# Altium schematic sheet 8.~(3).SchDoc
size 599 x 434 mm
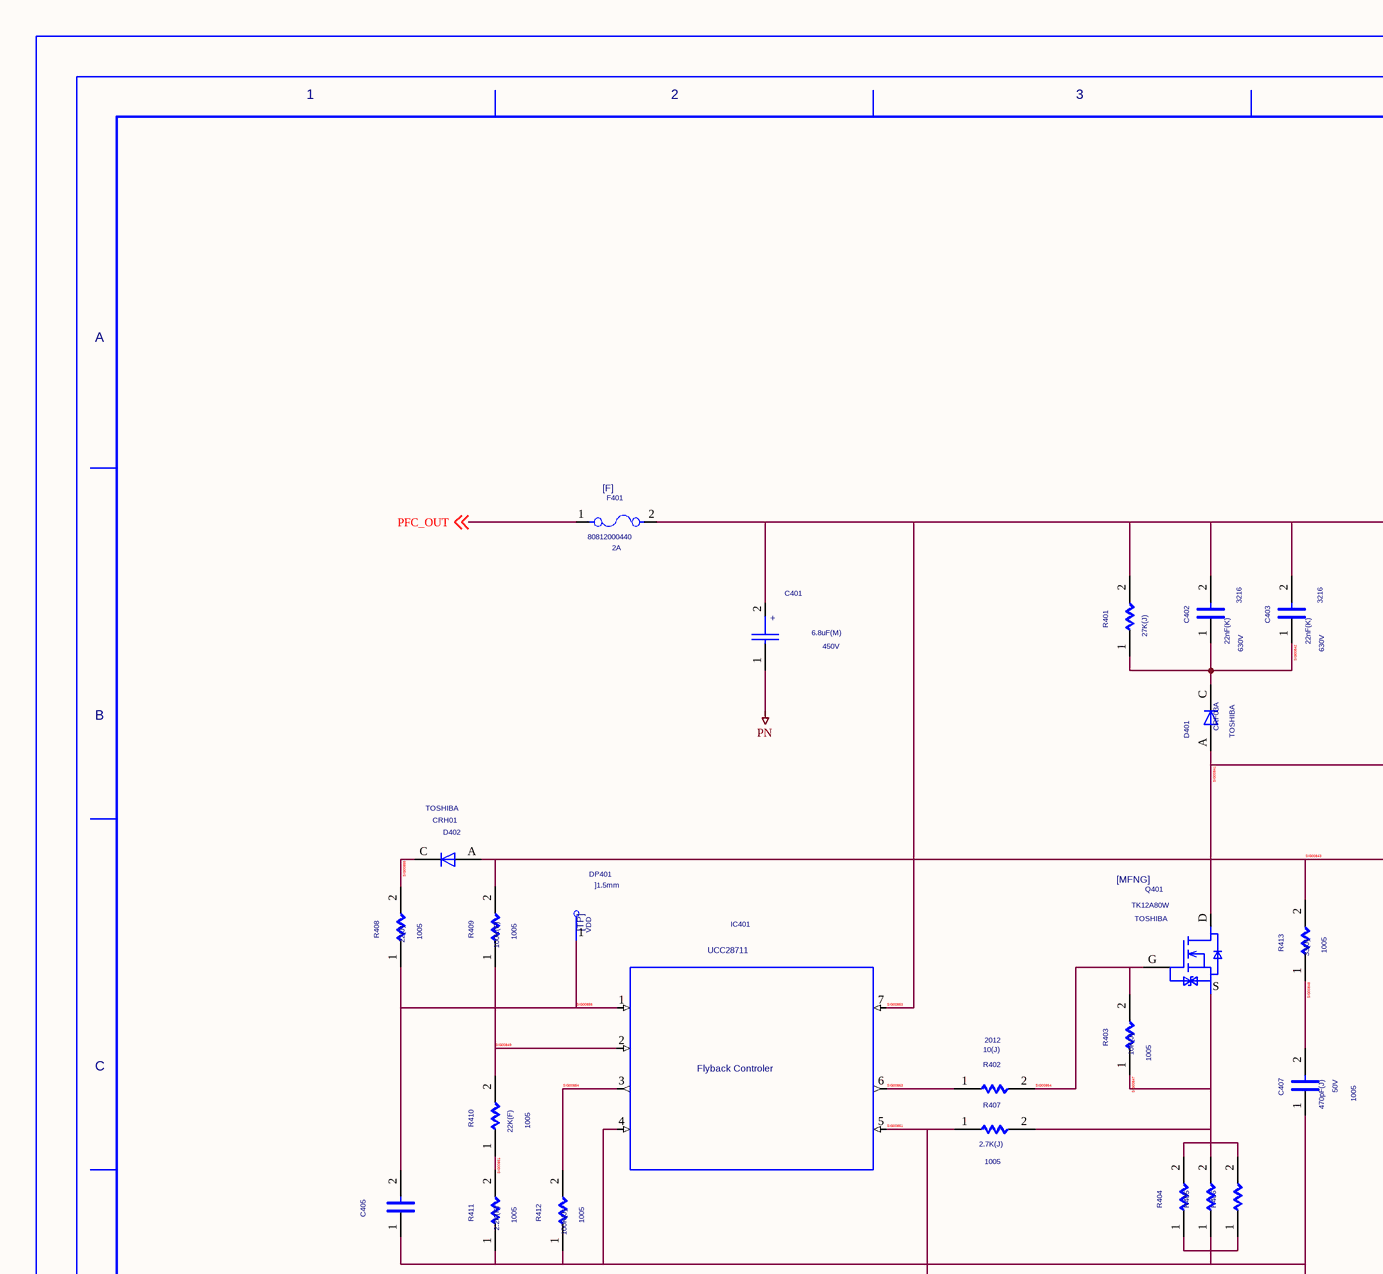
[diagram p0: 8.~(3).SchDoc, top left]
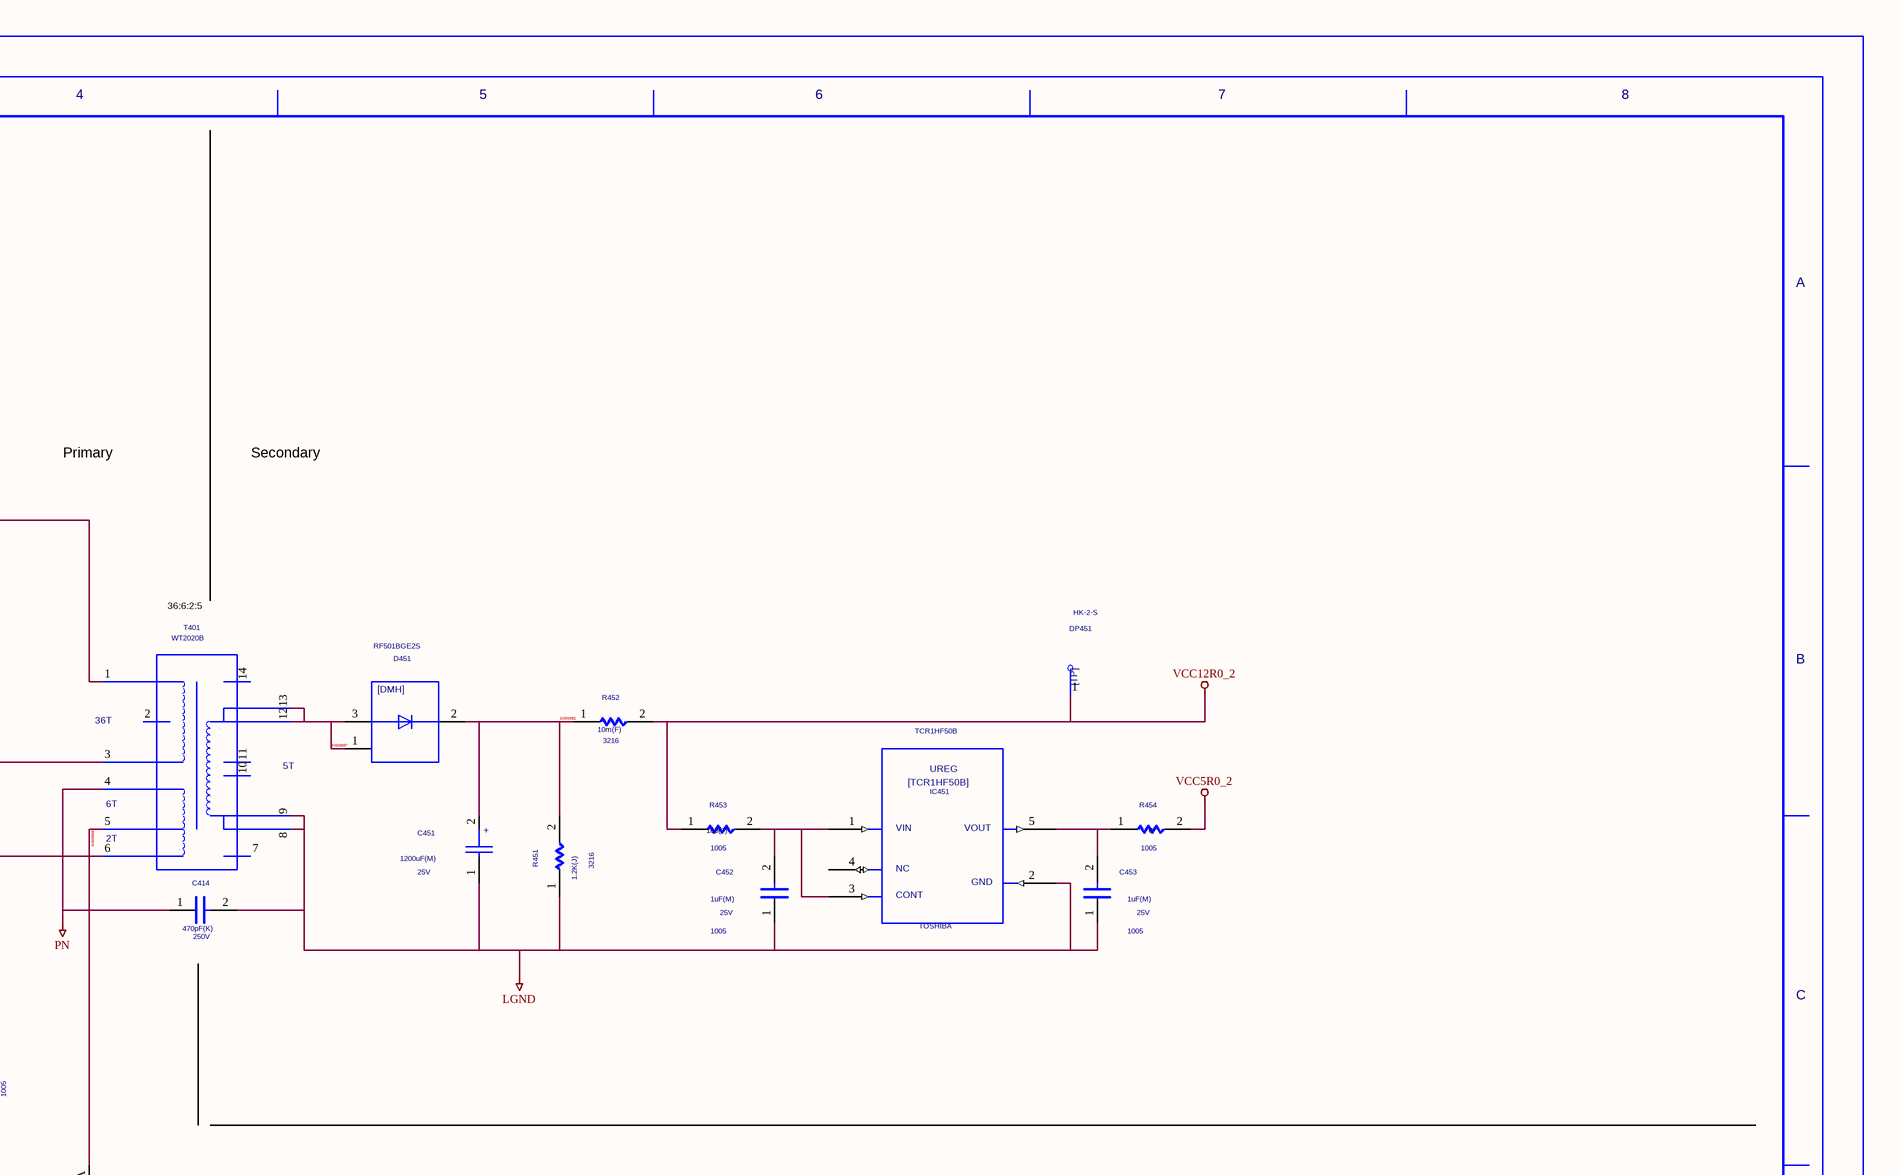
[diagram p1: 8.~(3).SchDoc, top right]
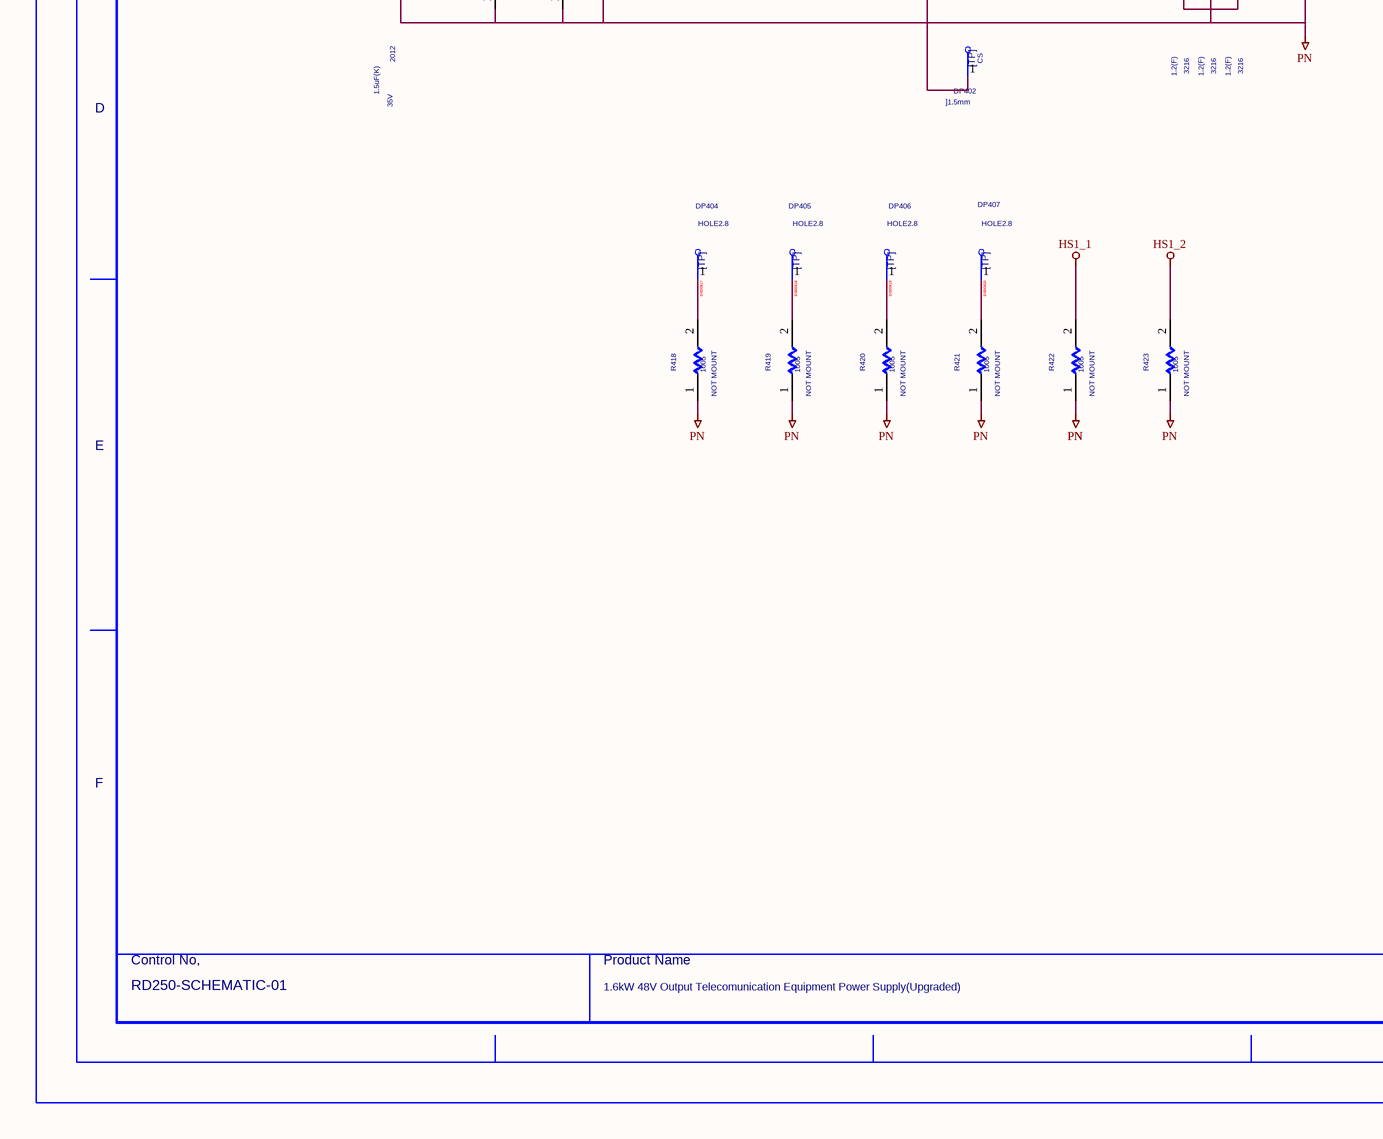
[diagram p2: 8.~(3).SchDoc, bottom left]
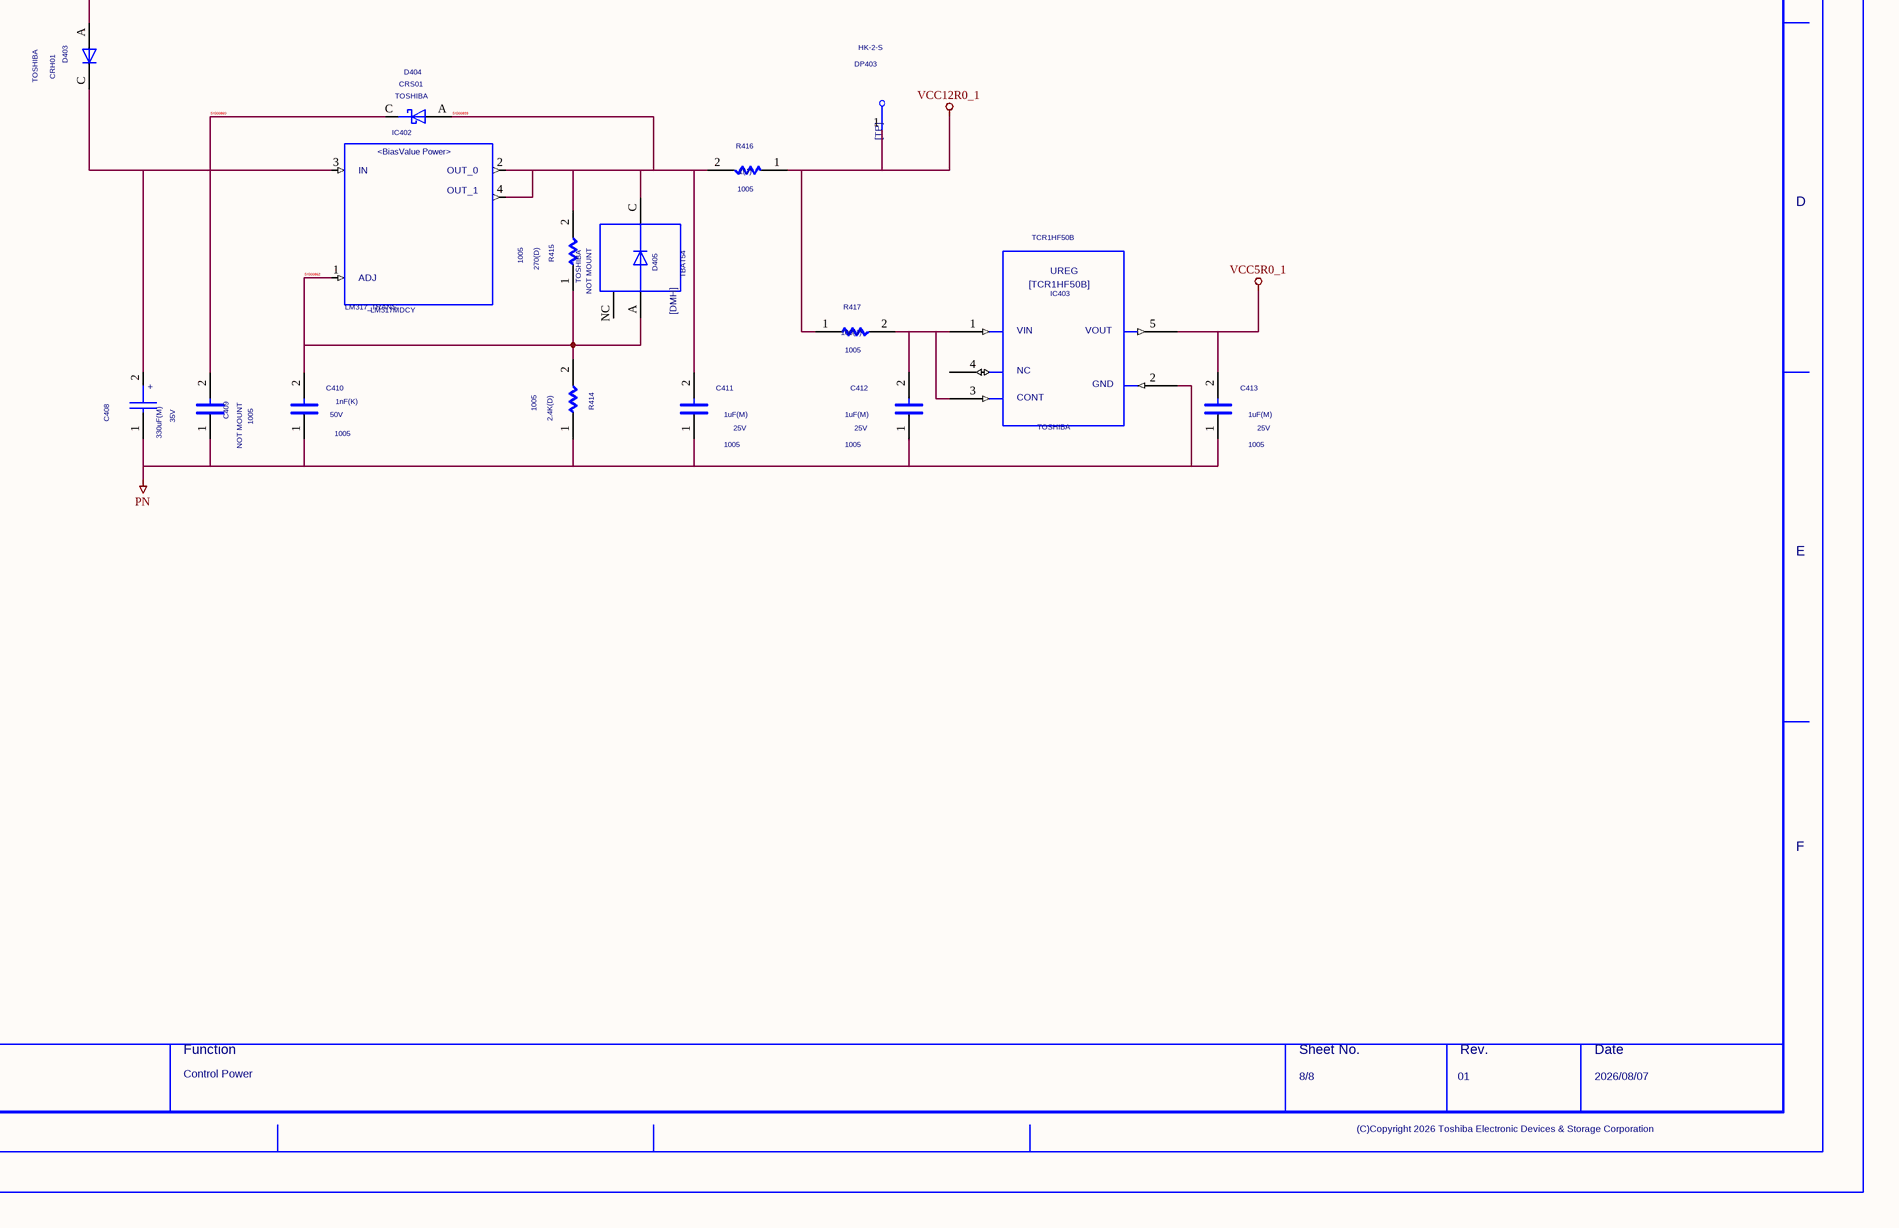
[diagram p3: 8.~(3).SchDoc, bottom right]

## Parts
C401  VAL1: 6.8uF(M)  VAL2: 450V  (hidden comment: CP)
C402  VAL1: 22nF(K)  VAL2: 630V  SIZECODESMD: 3216  (hidden comment: C)
C403  VAL1: 22nF(K)  VAL2: 630V  SIZECODESMD: 3216  (hidden comment: C)
C405  VAL1: 1.5uF(K)  VAL2: 35V  SIZECODESMD: 2012  (hidden comment: GRM21BC71E106KE01)
C407  VAL1: 470pF(J)  VAL2: 50V  SIZECODESMD: 1005  (hidden comment: C)
C408  VAL1: 330uF(M)  VAL2: 35V  (hidden comment: CP)
C409  NOTMOUNT: NOT MOUNT  SIZECODESMD: 1005  (hidden comment: C)
C410  VAL1: 1nF(K)  VAL2: 50V  SIZECODESMD: 1005  (hidden comment: C)
C411  VAL1: 1uF(M)  VAL2: 25V  SIZECODESMD: 1005  (hidden comment: C)
C412  VAL1: 1uF(M)  VAL2: 25V  SIZECODESMD: 1005  (hidden comment: C)
C413  VAL1: 1uF(M)  VAL2: 25V  SIZECODESMD: 1005  (hidden comment: C)
C414  VAL1: 470pF(K)  VAL2: 250V  (hidden comment: C)
C451  VAL1: 1200uF(M)  VAL2: 25V  (hidden comment: CP)
C452  VAL1: 1uF(M)  VAL2: 25V  SIZECODESMD: 1005  (hidden comment: C)
C453  VAL1: 1uF(M)  VAL2: 25V  SIZECODESMD: 1005  (hidden comment: C)
D401  USERCOMPTEXT3: TOSHIBA  VAL3: CRF03A  (hidden comment: D)
D402  USERCOMPTEXT3: TOSHIBA  VAL3: CRH01  (hidden comment: D)
D403  USERCOMPTEXT3: TOSHIBA  VAL3: CRH01  (hidden comment: D)
D404  USERCOMPTEXT3: TOSHIBA  VAL3: CRS01  (hidden comment: SBD)
D405  NOTMOUNT: NOT MOUNT  USERCOMPTEXT3: TOSHIBA  VAL3: TBAT54  (hidden comment: DMH)
D451  RF501BGE2S
DP401  COMPCOMMENT: VDD  USERCOMPTEXT1: ]1.5mm  (hidden comment: TP)
DP402  COMPCOMMENT: CS  USERCOMPTEXT1: ]1.5mm  (hidden comment: TP)
DP403  VAL3: HK-2-S  (hidden comment: TP)
DP404  VAL3: HOLE2.8  (hidden comment: TP)
DP405  VAL3: HOLE2.8  (hidden comment: TP)
DP406  VAL3: HOLE2.8  (hidden comment: TP)
DP407  VAL3: HOLE2.8  (hidden comment: TP)
DP451  VAL3: HK-2-S  (hidden comment: TP)
F401  VAL1: 2A  VAL3: 80812000440  (hidden comment: F)
IC401  UCC28711
IC402  LM317_TRANS  [DCY0004A_N]
IC403  USERCOMPTEXT3: TOSHIBA  (hidden comment: TCR1HF50B)
IC451  USERCOMPTEXT3: TOSHIBA  (hidden comment: TCR1HF50B)
Q401  USERCOMPTEXT3: TOSHIBA  VAL3: TK12A80W  (hidden comment: MFNF)
R401  VAL1: 27K(J)  (hidden comment: R)
R402  VAL1: 10(J)  SIZECODESMD: 2012  (hidden comment: R)
R403  VAL1: 10K(J)  SIZECODESMD: 1005  (hidden comment: R)
R404  VAL1: 1.2(F)  SIZECODESMD: 3216  (hidden comment: R)
R405  VAL1: 1.2(F)  SIZECODESMD: 3216  (hidden comment: R)
R406  VAL1: 1.2(F)  SIZECODESMD: 3216  (hidden comment: R)
R407  VAL1: 2.7K(J)  SIZECODESMD: 1005  (hidden comment: R)
R408  VAL1: 22(J)  SIZECODESMD: 1005  (hidden comment: R)
R409  VAL1: 100K(F)  SIZECODESMD: 1005  (hidden comment: R)
R410  VAL1: 22K(F)  SIZECODESMD: 1005  (hidden comment: R)
R411  VAL1: 2.2K(F)  SIZECODESMD: 1005  (hidden comment: R)
R412  VAL1: 100K(J)  SIZECODESMD: 1005  (hidden comment: R)
R413  VAL1: 33(J)  SIZECODESMD: 1005  (hidden comment: R)
R414  VAL1: 2.4K(D)  SIZECODESMD: 1005  (hidden comment: R)
R415  VAL1: 270(D)  SIZECODESMD: 1005  (hidden comment: R)
R416  VAL1: 1(J)  SIZECODESMD: 1005  (hidden comment: R)
R417  VAL1: 100(J)  SIZECODESMD: 1005  (hidden comment: R)
R418  NOTMOUNT: NOT MOUNT  SIZECODESMD: 1005  (hidden comment: R)
R419  NOTMOUNT: NOT MOUNT  SIZECODESMD: 1005  (hidden comment: R)
R420  NOTMOUNT: NOT MOUNT  SIZECODESMD: 1005  (hidden comment: R)
R421  NOTMOUNT: NOT MOUNT  SIZECODESMD: 1005  (hidden comment: R)
R422  NOTMOUNT: NOT MOUNT  SIZECODESMD: 1005  (hidden comment: R)
R423  NOTMOUNT: NOT MOUNT  SIZECODESMD: 1005  (hidden comment: R)
R451  VAL1: 1.2K(J)  SIZECODESMD: 3216  (hidden comment: R)
R452  USERCOMPTEXT1: 10m(F)  SIZECODESMD: 3216  (hidden comment: R)
R453  VAL1: 100(J)  SIZECODESMD: 1005  (hidden comment: R)
R454  VAL1: 0  SIZECODESMD: 1005  (hidden comment: R)
T401  T3_12V67A  (value not drawn)
U?  DATE: 2026/08/07  DRAWINGNUMBER: RD250-SCHEMATIC-01  TITLE: 1.6kW 48V Output Telecomunication / Equipment Power Supply(Upgraded)  FUNCTION: Control Power  SHEETNUMBER: 8/8  REVISION: 01  (hidden comment: WAKU_A3_TDSC_PSDEV_LOCAL)

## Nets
HS1_1: R422.2
HS1_2: R423.2
LGND: C414.2 C451.1 C452.1 C453.1 IC451.2 R451.1 T401.8 T401.9
PN: C401.1 C405.1 C407.1 C408.1 C409.1 C410.1 C411.1 C412.1 C413.1 C414.1 IC401.4 IC403.2 R404.1 R405.1 R406.1 R411.1 R412.1 R414.1 R418.1 R419.1 R420.1 R421.1 R422.1 R423.1 T401.4
VCC5R0_1: C413.2 IC403.5
VCC5R0_2: R454.2
VCC12R0_1: DP403.1 R416.1 R417.1
VCC12R0_2: DP451.1 R452.2 R453.1
PFC_OUT: F401.1 ; off-sheet PFC_OUT
SIG00817: DP404.1 R418.2
SIG00818: DP405.1 R419.2
SIG00819: DP406.1 R420.2
SIG00820: DP407.1 R421.2
SIG00823: C453.2 IC451.5 R454.1
SIG00826: C452.2 IC451.1 IC451.3 R453.2
SIG00837: D451.1 D451.3 T401.12 T401.13
SIG00839: C411.2 D404.A D405.C IC402.2 IC402.4 R415.2 R416.2
SIG00841: D401.A Q401.D T401.3
SIG00842: C402.1 C403.1 D401.C R401.1
SIG00843: D402.A R409.2 R413.2 T401.6
SIG00847: Q401.S R403.1 R404.2 R405.2 R406.2 R407.2
SIG00848: C407.2 R413.1
SIG00849: IC401.2 R409.1 R410.2
SIG00851: DP402.1 IC401.5 R407.1
SIG00852: C451.2 D451.2 R451.2 R452.1
SIG00853: C401.2 C402.2 C403.2 F401.2 IC401.7 R401.2 T401.1
SIG00854: IC401.3 R412.2
SIG00855: D402.C R408.2
SIG00856: C405.2 DP401.1 IC401.1 R408.1
SIG00858: C412.2 IC403.1 IC403.3 R417.2
SIG00859: D403.A T401.5
SIG00860: C409.2 D404.C
SIG00861: R410.1 R411.2
SIG00862: C410.2 D405.A IC402.1 R414.2 R415.1
SIG00863: IC401.6 R402.1
SIG00864: Q401.G R402.2 R403.2
NetC408_2: C408.2 D403.C IC402.3

Not connected (* = marked no-connect by the designer): D405 NC; IC403 4; IC451 4; T401 2 7 10 11 14

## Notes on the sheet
- Primary
- Secondary
- 36:6:2:5

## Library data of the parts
C401 = CP: SAVEAREA0: -1450,-153,20294,13055; SAVECOUNT: 52; TIME: 15:02:55; UPDATEUSER: fukuda-y; UPDATETIME: 16:13:42; OriginalSymbolOrigin: (2540,10160); VAL3: EKXJ451ELL6R8MJ16S; COMP: PRT_3; CHIPSIZE: D10xL22; MAXGCOUNT: 1; SIZECODESMD: DIP
C402 C403 = C: OriginalSymbolOrigin: (2540,7620); COMP: PRT_46; SAVECOUNT: 0
C405 = GRM21BC71E106KE01: TIME: 10:25:11; UPDATEUSER: t4887876; UPDATETIME: 16:23:00; SAVECOUNT: 11; MAKER: Murata; OriginalSymbolOrigin: (2540,7620); CHIPSIZE: 1005; MAXGCOUNT: 1
C407 C409 C410 = C_Dup1: OriginalSymbolOrigin: (2540,7620); COMP: PRT_52; SAVECOUNT: 0
C408 = CP: SAVEAREA0: -1450,-153,20294,13055; SAVECOUNT: 52; TIME: 15:02:55; UPDATEUSER: fukuda-y; UPDATETIME: 16:13:42; OriginalSymbolOrigin: (2540,10160); SIZECODESMD: 1010; COMP: EMLA350ARA331MJA0G
C411-C413 C452 C453 = C_Dup1: SQ_PART_MODEL: CON_1U; OriginalSymbolOrigin: (2540,7620); COMP: PRT_52; MAXGCOUNT: 1; ADSCNVFLAG: ON; ADSCOMPONENTNAME: C_1608; SAVECOUNT: 0
C414 = C_Dup1: OriginalSymbolOrigin: (2540,7620); VAL3: DE2B3SA221KA3BT02F; SAVECOUNT: 0
C451 = CP: SAVEAREA0: -1450,-153,20294,13055; SAVECOUNT: 52; TIME: 15:02:55; UPDATEUSER: fukuda-y; UPDATETIME: 16:13:42; OriginalSymbolOrigin: (2540,10160); VAL3: EKZN250ELL122MJ25S; SIZECODESMD: DIP; COMP: PRT_3
D401 = D_Dup1: SAVEAREA0: -225,-91,12804,7836; SAVECOUNT: 3; TIME: 14:49:55; UPDATEUSER: 19870035; UPDATETIME: 14:20:16; OriginalSymbolOrigin: (5080,5080); USERCOMPTEXT2: 600V,0.7A
D402 D403 = D: SAVEAREA0: -225,-91,12804,7836; SAVECOUNT: 3; TIME: 14:49:55; UPDATEUSER: 19870035; UPDATETIME: 14:20:16; OriginalSymbolOrigin: (5080,5080); USERCOMPTEXT2: 200V,1A; MAXGCOUNT: 1; ADSCNVFLAG: ON; ADSCOMPONENTNAME: D_D; COMP: GDM420000387
D404 = SBD: SAVEAREA0: -4630,-153,17114,13055; TIME: 14:49:55; UPDATEUSER: fukuda-y; UPDATETIME: 08:16:22; SAVECOUNT: 9; OriginalSymbolOrigin: (5080,5080); USERCOMPTEXT2: 30V,1A; MAXGCOUNT: 1; COMP: K4200730; ADSCNVFLAG: ON; ADSCOMPONENTNAME: D_SBD
D405 = DMH: SAVEAREA0: -4931,-287,27399,20979; TIME: 08:58:08; UPDATEUSER: kishi-s; UPDATETIME: 09:01:52; SAVECOUNT: 2; OriginalSymbolOrigin: (5080,17780); USERCOMPTEXT2: 30V,0.2A; COMP: PRT_25
D451 = RF501BGE2S: SAVEAREA0: -4931,-287,27399,20979; TIME: 08:58:08; UPDATEUSER: t6860224; UPDATETIME: 11:55:12; SAVECOUNT: 3; OriginalSymbolOrigin: (5080,17780); USERCOMPTEXT3: #%ﾘ%; MAXGCOUNT: 1; COMP: NJM78M05SDL1_TE1; ADSCNVFLAG: ON; ADSCOMPONENTNAME: D_SBDMB
DP401 DP402 = TP: TIME: 16:12:21; UPDATEUSER: fukuda-y; UPDATETIME: 16:18:11; SAVECOUNT: 2; SAVEAREA0: -242,-92,12810,7836; OriginalSymbolOrigin: (0,7620); COMP: DTP815
DP403 DP451 = TP: TIME: 16:12:21; UPDATEUSER: fukuda-y; UPDATETIME: 16:18:11; SAVECOUNT: 2; SAVEAREA0: -242,-92,12810,7836; OriginalSymbolOrigin: (0,7620); COMP: PRT_44
DP404-DP407 = TP: TIME: 16:12:21; UPDATEUSER: fukuda-y; UPDATETIME: 16:18:11; SAVECOUNT: 2; SAVEAREA0: -242,-92,12810,7836; OriginalSymbolOrigin: (0,7620); COMP: PRT_39; CHIPSIZE: Through Hole
F401 = F: OriginalSymbolOrigin: (2540,5080); SAVECOUNT: 0
IC401 = UCC28711DR: PSPICETEMPLATE: X^@REFDES %CS %VS %CBC %DRV %VDD %GND %HV @MODEL; TIME: 16:40:05; UPDATEUSER: t4887876; UPDATETIME: 09:12:44; SAVECOUNT: 14; SAVEAREA0: -40606,-13411,99691,50516; OriginalSymbolOrigin: (2540,38100)
IC402 = LM317MDCY: ALTERNATE PARTNUMBER: LM317DCY; PARTNUMBER: LM317DCYR; MANUFACTURER: Texas Instruments; PIN_COUNT: 4; SYMBOLCREATER: Altium; DEVICESINPACKAGE: 1; ISHETEROGENEOUS: False; DEVICEDESIGNATOR: A; DEVICENUMBERING: Alpha; PSPICETEMPLATE: X^@REFDES %IN %ADJ %OUT_0 %OUT_1 @MODEL; ORIGINALSYMBOLORIGIN: (2540,30480); COMPTYPE: IC; TIME: 16:40:05; UPDATEUSER: t6860224; UPDATETIME: 16:01:55; SAVECOUNT: 6; SAVEAREA0: -16909,0,49982,30480; FUNCTION: FXD
IC403 IC451 = TCR1HF50B: SAVEAREA0: -444,-3509,43701,41525; TIME: 18:31:00; UPDATEUSER: t6860224; UPDATETIME: 12:58:25; SAVECOUNT: 21; OriginalSymbolOrigin: (7620,35560)
Q401 = MFNG: SAVECOUNT: 11; SAVEAREA0: -7084,-293,21840,15991; OriginalSymbolOrigin: (5080,12700); MAXGCOUNT: 1; ADSCNVFLAG: ON; ADSCOMPONENTNAME: Q_MFNG; PIN NAMES VISIBLE: False; COMP: K4100860; PIN NAMES ROTATE: True
R401 = R: VAL2: 3W; OriginalSymbolOrigin: (5080,5080); VAL3: PR03000202702JAC00; COMP: PRT_54; SIZECODESMD: TH; SAVECOUNT: 0
R402 = R: VAL2: 250mW; OriginalSymbolOrigin: (5080,5080); COMP: R2012; SAVECOUNT: 0
R403 R408-R413 = R: VAL2: 63mW; OriginalSymbolOrigin: (5080,5080); MAXGCOUNT: 1; COMP: GDM010004481; SAVECOUNT: 0
R404-R406 = R: VAL2: 250mW; OriginalSymbolOrigin: (5080,5080); COMP: R3216; SAVECOUNT: 0
R407 = R: VAL2: 63mW; OriginalSymbolOrigin: (5080,5080); COMP: GDM010004481; SAVECOUNT: 0
R414 R415 = R_Dup1: VAL2: 63mW; OriginalSymbolOrigin: (5080,5080); MAXGCOUNT: 1; COMP: GDM010004481; SAVECOUNT: 0
R416 = R_Dup1: SQ_PART_MODEL: RES_0; VAL2: 63mW; OriginalSymbolOrigin: (5080,5080); COMP: GDM010004481; CHIPSIZE: 1608; MAXGCOUNT: 1; ADSCNVFLAG: ON; ADSCOMPONENTNAME: R_1005; SAVECOUNT: 0
R417 R453 = R_Dup1: VAL2: 63mW; OriginalSymbolOrigin: (5080,5080); COMP: GDM010004481; CHIPSIZE: 1608; MAXGCOUNT: 1; SAVECOUNT: 0
R418-R423 = R_Dup1: SQ_PART_MODEL: RES_0; OriginalSymbolOrigin: (5080,5080); COMP: GDM010004481; CHIPSIZE: 1608; MAXGCOUNT: 1; ADSCNVFLAG: ON; ADSCOMPONENTNAME: R_1005; SAVECOUNT: 0
R451 R452 = R: VAL2: 250mW; OriginalSymbolOrigin: (5080,5080); COMP: PRT_5; SAVECOUNT: 0
R454 = R_Dup1: SQ_PART_MODEL: RES_0; VAL2: 63mW; OriginalSymbolOrigin: (5080,5080); COMP: GDM010004481; CHIPSIZE: 1608; MAXGCOUNT: 1; ADSCNVFLAG: ON; ADSCOMPONENTNAME: R_1005
T401 = WT2020B: UPDATEUSER: t4887876; UPDATETIME: 11:02:48; SAVECOUNT: 21; TIME: 16:40:06; SAVEAREA0: -85659,-25353,110804,64166; ORIGINALSYMBOLORIGIN: (0,40640); VAL1: spec = YB-3513A; VAL2: 36:6:2:5
U? = WAKU_A3_TDSC_PSDEV_LOCAL: PLOTTIME: HH:MM; SAVEAREA0: -311037,-554865,914355,115662; TIME: 18:12:27; UPDATEUSER: t5459927; UPDATETIME: 11:24:38; SAVECOUNT: 3; ZONEOFFSETX: 36; ZONEOFFSETY: -24; OriginalSymbolOrigin: (0,434340); SHTSAVECOUNT: 194; PAGENUMBER: 8; DESIGNED: TOSHIBA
